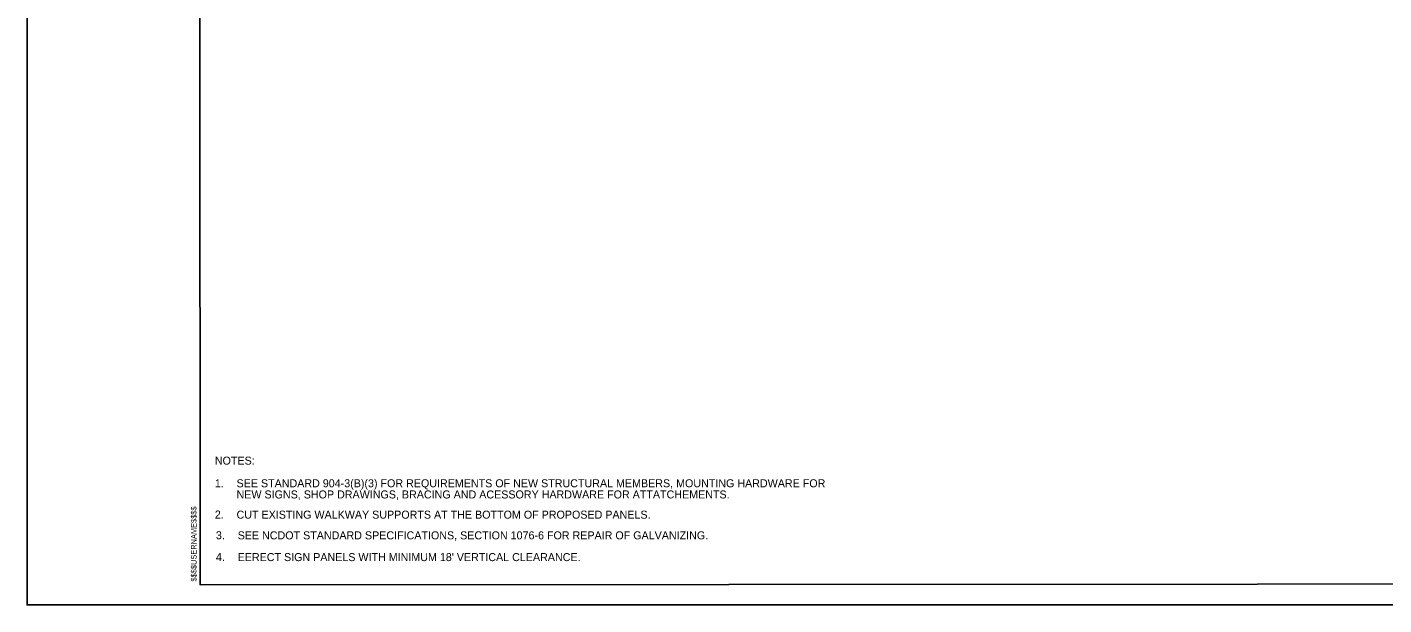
# Model space of a CAD drawing. Extents: x 1726790 to 1728895, y 539219 to 541550.
# Drawn here: x 1727261.5 to 1727517.9, y 539383.1 to 539492.3 of the extents above; entities that cross this region are included whole.
import ezdxf

# ---------------------------------------------------------------- set-up
doc = ezdxf.new("R2010")
doc.units = 0
for name, color, linetype in [('Overhead Sheet Border', 7, 'Continuous'), ('Overhead Sheet Text', 7, 'Continuous'), ('Sheet Plot Border Outside CELL', 7, 'Continuous')]:
    doc.layers.add(name, color=color, linetype=linetype)

msp = doc.modelspace()

# ---------------------------------------------------------------- linework, layer by layer
at = {"layer": 'Overhead Sheet Border'}
msp.add_lwpolyline([(1727593.82, 539596.91), (1727294.08, 539596.75), (1727294.19, 539386.93), (1727593.93, 539387.09)], close=True, dxfattribs=at)
at = {"layer": 'Sheet Plot Border Outside CELL'}
msp.add_lwpolyline([(1727598.07, 539602.3), (1727261.51, 539602.3), (1727261.51, 539383.13), (1727598.07, 539383.13)], close=True, dxfattribs=at)

# ---------------------------------------------------------------- texts
at = {"layer": 'Overhead Sheet Text'}
for s, height, p in [('NOTES:', 1.513, (1727296.98, 539409.63)), ('1.', 1.513, (1727296.98, 539405.35)), ('SEE STANDARD 904-3(B)(3) FOR REQUIREMENTS OF NEW STRUCTURAL MEMBERS, MOUNTING HARDWARE FOR', 1.5128, (1727301.08, 539405.35)), ('NEW SIGNS, SHOP DRAWINGS, BRACING AND ACESSORY HARDWARE FOR ATTATCHEMENTS.', 1.5128, (1727301.08, 539403.24)), ('2.', 1.513, (1727296.98, 539399.44)), ('CUT EXISTING WALKWAY SUPPORTS AT THE BOTTOM OF PROPOSED PANELS.', 1.5128, (1727301.08, 539399.42)), ('3.', 1.513, (1727297.18, 539395.53)), ('SEE NCDOT STANDARD SPECIFICATIONS, SECTION 1076-6 FOR REPAIR OF GALVANIZING.', 1.5128, (1727301.29, 539395.51)), ('4.', 1.513, (1727297.18, 539391.42)), ("EERECT SIGN PANELS WITH MINIMUM 18' VERTICAL CLEARANCE.", 1.5128, (1727301.29, 539391.4))]:
    msp.add_text(s, height=height, dxfattribs=at).set_placement(p)
msp.add_text('$$$$USERNAME$$$$', height=1.0491, rotation=90.0308, dxfattribs=at).set_placement((1727293.53, 539387.54))

doc.saveas('drawing.dxf')
